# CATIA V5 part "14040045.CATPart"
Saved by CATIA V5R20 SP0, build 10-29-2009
Part number: 14040045
Definition: NONE
Nomenclature: 14040045
Source: Unknown
Description: 14040045
Bounding box of the stored display mesh (mm): x -22.5 to 90, y -34 to 23.924, z -24.1 to 24.1
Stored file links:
  C:\Users\Utente\Desktop\IO LAVORO\3D X SITO CF\X SITO\PLASTICA\RF2\14040045.CATPart
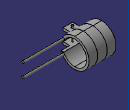
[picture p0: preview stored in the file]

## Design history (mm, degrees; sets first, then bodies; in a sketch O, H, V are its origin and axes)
Body1 "14040045" (main body)
  Solid1: solid without history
